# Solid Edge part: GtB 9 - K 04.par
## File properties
Author: Carsten
Template: Normal.par
Last saved by: Carsten
Revision: 4
Application: Solid Edge
Genauigkeit: 0,990
Teilflächenrmatvorlage: Model Default
Coef. of Thermal Exp: 0.0
Thermal Conductivity: 0.0
Specific Heat: 0.0
Modulus of Elasticity: 0.0
Poission's Ratio: 0.0
Yield Stress: 0.0
Ultimate Stress: 0.0
Elongation: 0.0
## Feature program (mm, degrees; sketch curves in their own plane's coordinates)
sketch for "unnamed Protrusion 1" plane through (0, 0, 0) normal (0, -1, 0) x-axis (1, 0, 0)
  line (-39.7762, 29.9319) -> (45.2238, 29.9319)
  line (45.2238, 29.9319) -> (45.2238, -80.0681)
  line (45.2238, -80.0681) -> (-39.7762, -80.0681)
  line (-39.7762, -80.0681) -> (-39.7762, 29.9319)
extrude "unnamed Protrusion 1" add finite 75 along -normal
sketch for "Ausschnitt_1" #1 plane through (2.7238, 0, -25.0681) normal (0, -1, 0) x-axis (1, 0, 0)
  line (-12.5, 25) -> (32.5, 25)
  line (32.5, 25) -> (32.5, -15)
  line (32.5, -15) -> (-12.5, -15)
  line (-12.5, -15) -> (-12.5, 25)
sketch for "Ausschnitt_1" #2 plane through (2.7238, 0, -25.0681) normal (0, -1, 0) x-axis (1, 0, 0)
  line (-42.5, 55) -> (-17.5, 55)
  line (-42.5, -10) -> (-17.5, 55)
  line (-42.5, 55) -> (-42.5, -10)
extrude "Ausschnitt_1" cut finite 107.95 along -normal
sketch for "Ausschnitt_2" plane through (45.2238, 37.5, -25.0681) normal (1, 0, 0) x-axis (0, 1, 0)
  line (-32.5, -55) -> (-32.5, -30)
  line (-32.5, -30) -> (27.5, -30)
  line (27.5, -30) -> (27.5, -55)
  line (27.5, -55) -> (-32.5, -55)
  dimension (linear) = 32.5
  dimension (linear) = 32.5
extrude "Ausschnitt_2" cut finite 123.825 along -normal
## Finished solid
Body 1: solid body, 15 faces, 39 edges, 26 vertices.
  Faces by surface: plane 15
  Edges by curve: line 39
Bounding box of the edges (mm): 85.000 x 75.000 x 110.000, from (-39.7762, 0, -80.0681) to (45.2238, 75, 29.9319).
Planar faces by outward normal: +x 2, +y 2, +z 2, -x 2, -y 2, -z 4, oblique 1
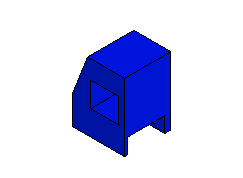
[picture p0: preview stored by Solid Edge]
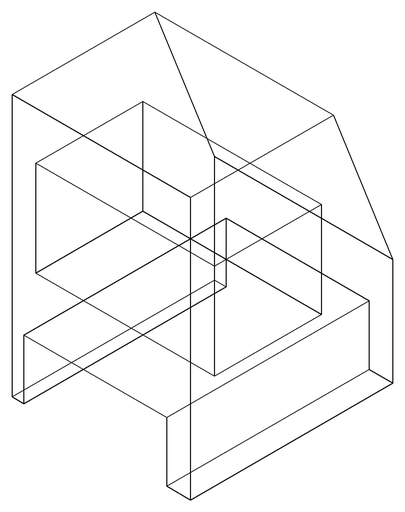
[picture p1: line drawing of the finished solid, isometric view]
